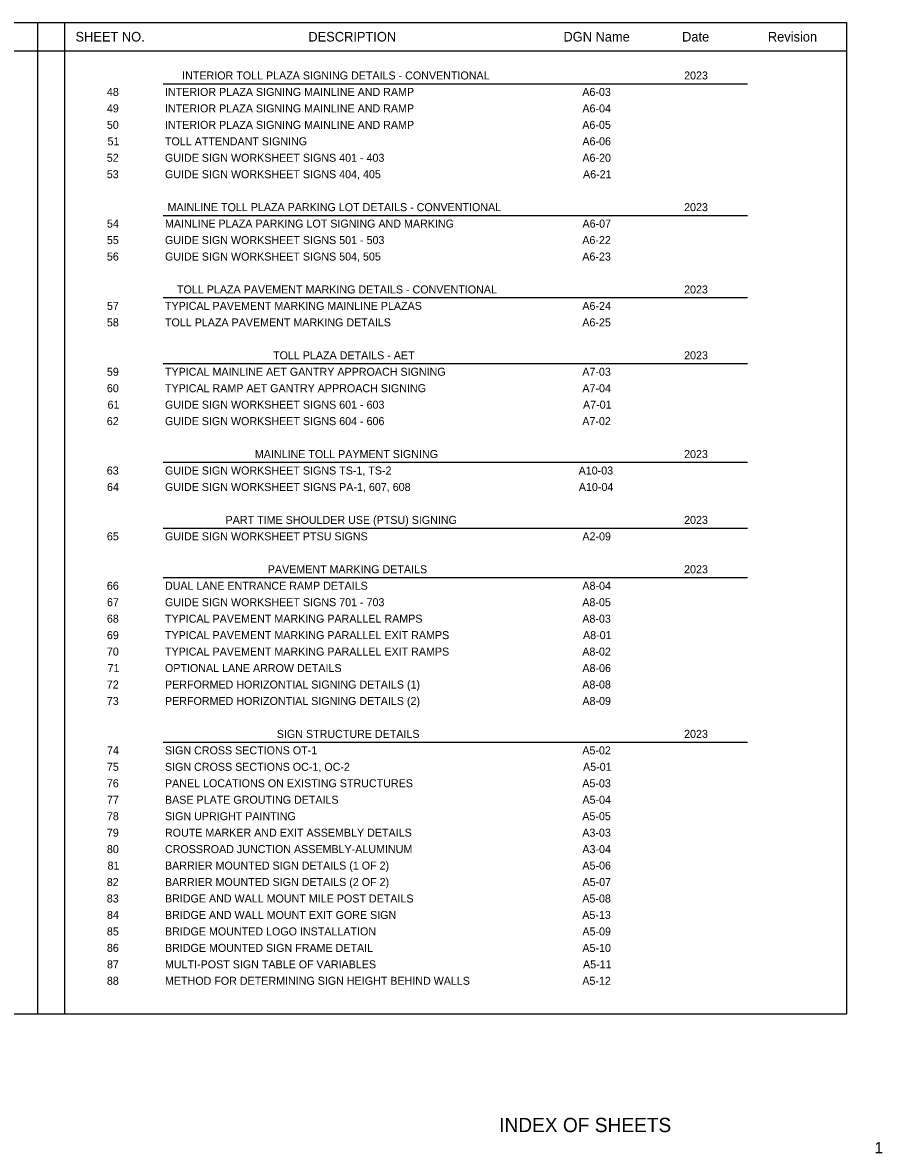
# Model space of a CAD drawing. Extents: x 2479979.8 to 2480018.9, y 3680687.9 to 3680700.6.
# Drawn here: x 2479989.84 to 2479999.24, y 3680688.19 to 3680700.55 of the extents above; entities that cross this region are included whole.
import ezdxf

# ---------------------------------------------------------------- set-up
doc = ezdxf.new("R2010")
doc.units = 0
for name, color, linetype in [('SumBoxLines_dp', 7, 'Continuous'), ('TextLabel', 7, 'Continuous'), ('TextMisc', 7, 'Continuous'), ('TextShtNo', 7, 'Continuous')]:
    doc.layers.add(name, color=color, linetype=linetype)

msp = doc.modelspace()

# ---------------------------------------------------------------- linework, layer by layer
at = {"layer": 'SumBoxLines_dp'}
for p, q in [((2479981.458, 3680700.555), (2479998.85, 3680700.555)), ((2479990.008, 3680700.555), (2479990.008, 3680689.717)), ((2479990.3, 3680700.555), (2479990.3, 3680690.167)), ((2479990.3, 3680700.555), (2479990.3, 3680689.717)), ((2479998.85, 3680700.555), (2479998.85, 3680689.717)), ((2479981.458, 3680700.247), (2479998.85, 3680700.247)), ((2479981.458, 3680700.247), (2479998.85, 3680700.247)), ((2479990.008, 3680700.247), (2479990.008, 3680691.427)), ((2479991.38, 3680699.887), (2479997.77, 3680699.887)), ((2479991.38, 3680699.887), (2479997.77, 3680699.887)), ((2479991.38, 3680698.447), (2479997.77, 3680698.447)), ((2479991.38, 3680698.447), (2479997.77, 3680698.447)), ((2479991.38, 3680697.547), (2479997.77, 3680697.547)), ((2479991.38, 3680697.547), (2479997.77, 3680697.547)), ((2479991.38, 3680696.827), (2479997.77, 3680696.827)), ((2479991.38, 3680696.827), (2479997.77, 3680696.827)), ((2479991.38, 3680695.747), (2479997.77, 3680695.747)), ((2479991.38, 3680695.747), (2479997.77, 3680695.747)), ((2479991.38, 3680695.027), (2479997.77, 3680695.027)), ((2479991.38, 3680695.027), (2479997.77, 3680695.027)), ((2479991.38, 3680694.487), (2479997.77, 3680694.487)), ((2479991.38, 3680694.487), (2479997.77, 3680694.487)), ((2479991.38, 3680692.687), (2479997.77, 3680692.687)), ((2479991.38, 3680692.687), (2479997.77, 3680692.687)), ((2479981.458, 3680689.717), (2479998.85, 3680689.717))]:
    msp.add_line(p, q, dxfattribs=at)

# ---------------------------------------------------------------- texts
at = {"layer": 'TextLabel'}
for s, height, p in [('SHEET NO.', 0.105, (2479990.422, 3680700.348)), ('DESCRIPTION', 0.105, (2479992.968, 3680700.348)), ('DGN Name', 0.105, (2479995.757, 3680700.348)), ('Date', 0.105, (2479997.054, 3680700.348)), ('Revision', 0.105, (2479997.992, 3680700.348)), ('INTERIOR TOLL PLAZA SIGNING DETAILS - CONVENTIONAL', 0.0875, (2479991.588, 3680699.933)), ('2023', 0.0875, (2479997.076, 3680699.933)), ('48', 0.0875, (2479990.765, 3680699.753)), ('INTERIOR PLAZA SIGNING MAINLINE AND RAMP', 0.0875, (2479991.4, 3680699.753)), ('A6-03', 0.0875, (2479995.963, 3680699.753)), ('49', 0.0875, (2479990.765, 3680699.573)), ('INTERIOR PLAZA SIGNING MAINLINE AND RAMP', 0.0875, (2479991.4, 3680699.573)), ('A6-04', 0.0875, (2479995.964, 3680699.573)), ('50', 0.0875, (2479990.765, 3680699.393)), ('INTERIOR PLAZA SIGNING MAINLINE AND RAMP', 0.0875, (2479991.4, 3680699.393)), ('A6-05', 0.0875, (2479995.963, 3680699.393)), ('51', 0.0875, (2479990.772, 3680699.213)), ('TOLL ATTENDANT SIGNING', 0.0875, (2479991.4, 3680699.213)), ('A6-06', 0.0875, (2479995.964, 3680699.213)), ('52', 0.0875, (2479990.764, 3680699.033)), ('GUIDE SIGN WORKSHEET SIGNS 401 - 403', 0.0875, (2479991.4, 3680699.033)), ('A6-20', 0.0875, (2479995.964, 3680699.033)), ('53', 0.0875, (2479990.764, 3680698.853)), ('GUIDE SIGN WORKSHEET SIGNS 404, 405', 0.0875, (2479991.4, 3680698.853)), ('A6-21', 0.0875, (2479995.971, 3680698.853)), ('MAINLINE TOLL PLAZA PARKING LOT DETAILS - CONVENTIONAL', 0.0875, (2479991.428, 3680698.493)), ('2023', 0.0875, (2479997.076, 3680698.493)), ('54', 0.0875, (2479990.766, 3680698.313)), ('MAINLINE PLAZA PARKING LOT SIGNING AND MARKING', 0.0875, (2479991.4, 3680698.313)), ('A6-07', 0.0875, (2479995.965, 3680698.313)), ('55', 0.0875, (2479990.765, 3680698.133)), ('GUIDE SIGN WORKSHEET SIGNS 501 - 503', 0.0875, (2479991.4, 3680698.133)), ('A6-22', 0.0875, (2479995.963, 3680698.133)), ('56', 0.0875, (2479990.765, 3680697.953)), ('GUIDE SIGN WORKSHEET SIGNS 504, 505', 0.0875, (2479991.4, 3680697.953)), ('A6-23', 0.0875, (2479995.963, 3680697.953)), ('TOLL PLAZA PAVEMENT MARKING DETAILS - CONVENTIONAL', 0.0875, (2479991.532, 3680697.593)), ('2023', 0.0875, (2479997.076, 3680697.593)), ('57', 0.0875, (2479990.766, 3680697.413)), ('TYPICAL PAVEMENT MARKING MAINLINE PLAZAS', 0.0875, (2479991.4, 3680697.413)), ('A6-24', 0.0875, (2479995.964, 3680697.413)), ('58', 0.0875, (2479990.765, 3680697.233)), ('TOLL PLAZA PAVEMENT MARKING DETAILS', 0.0875, (2479991.4, 3680697.233)), ('A6-25', 0.0875, (2479995.963, 3680697.233)), ('TOLL PLAZA DETAILS - AET', 0.0875, (2479992.582, 3680696.873)), ('2023', 0.0875, (2479997.076, 3680696.873)), ('59', 0.0875, (2479990.765, 3680696.693)), ('TYPICAL MAINLINE AET GANTRY APPROACH SIGNING', 0.0875, (2479991.4, 3680696.693)), ('A7-03', 0.0875, (2479995.963, 3680696.693)), ('60', 0.0875, (2479990.765, 3680696.513)), ('TYPICAL RAMP AET GANTRY APPROACH SIGNING', 0.0875, (2479991.4, 3680696.513)), ('A7-04', 0.0875, (2479995.964, 3680696.513)), ('61', 0.0875, (2479990.772, 3680696.333)), ('GUIDE SIGN WORKSHEET SIGNS 601 - 603', 0.0875, (2479991.4, 3680696.333)), ('A7-01', 0.0875, (2479995.971, 3680696.333)), ('62', 0.0875, (2479990.764, 3680696.153)), ('GUIDE SIGN WORKSHEET SIGNS 604 - 606', 0.0875, (2479991.4, 3680696.153)), ('A7-02', 0.0875, (2479995.963, 3680696.153)), ('MAINLINE TOLL PAYMENT SIGNING', 0.0875, (2479992.383, 3680695.793)), ('2023', 0.0875, (2479997.076, 3680695.793)), ('63', 0.0875, (2479990.764, 3680695.613)), ('GUIDE SIGN WORKSHEET SIGNS TS-1, TS-2', 0.0875, (2479991.4, 3680695.613)), ('A10-03', 0.0875, (2479995.923, 3680695.613)), ('64', 0.0875, (2479990.766, 3680695.433)), ('GUIDE SIGN WORKSHEET SIGNS PA-1, 607, 608', 0.0875, (2479991.4, 3680695.433)), ('A10-04', 0.0875, (2479995.925, 3680695.433)), ('PART TIME SHOULDER USE (PTSU) SIGNING', 0.0875, (2479992.063, 3680695.073)), ('2023', 0.0875, (2479997.076, 3680695.073)), ('65', 0.0875, (2479990.765, 3680694.893)), ('GUIDE SIGN WORKSHEET PTSU SIGNS', 0.0875, (2479991.4, 3680694.893)), ('A2-09', 0.0875, (2479995.964, 3680694.893)), ('PAVEMENT MARKING DETAILS', 0.0875, (2479992.524, 3680694.533)), ('2023', 0.0875, (2479997.076, 3680694.533)), ('66', 0.0875, (2479990.765, 3680694.353)), ('DUAL LANE ENTRANCE RAMP DETAILS', 0.0875, (2479991.4, 3680694.353)), ('A8-04', 0.0875, (2479995.964, 3680694.353)), ('67', 0.0875, (2479990.766, 3680694.173)), ('GUIDE SIGN WORKSHEET SIGNS 701 - 703', 0.0875, (2479991.4, 3680694.173)), ('A8-05', 0.0875, (2479995.963, 3680694.173)), ('68', 0.0875, (2479990.765, 3680693.993)), ('TYPICAL PAVEMENT MARKING PARALLEL RAMPS', 0.0875, (2479991.4, 3680693.993)), ('A8-03', 0.0875, (2479995.963, 3680693.993)), ('69', 0.0875, (2479990.765, 3680693.813)), ('TYPICAL PAVEMENT MARKING PARALLEL EXIT RAMPS', 0.0875, (2479991.4, 3680693.813)), ('A8-01', 0.0875, (2479995.971, 3680693.813)), ('70', 0.0875, (2479990.765, 3680693.633)), ('TYPICAL PAVEMENT MARKING PARALLEL EXIT RAMPS', 0.0875, (2479991.4, 3680693.633)), ('A8-02', 0.0875, (2479995.963, 3680693.633)), ('71', 0.0875, (2479990.772, 3680693.453)), ('OPTIONAL LANE ARROW DETAILS', 0.0875, (2479991.4, 3680693.453)), ('A8-06', 0.0875, (2479995.964, 3680693.453)), ('PERFORMED HORIZONTIAL SIGNING DETAILS (1)', 0.0875, (2479991.4, 3680693.273)), ('72', 0.0875, (2479990.764, 3680693.273)), ('A8-08', 0.0875, (2479995.963, 3680693.273)), ('73', 0.0875, (2479990.764, 3680693.093)), ('PERFORMED HORIZONTIAL SIGNING DETAILS (2)', 0.0875, (2479991.4, 3680693.093)), ('A8-09', 0.0875, (2479995.964, 3680693.093)), ('SIGN STRUCTURE DETAILS', 0.0875, (2479992.623, 3680692.733)), ('2023', 0.0875, (2479997.076, 3680692.733)), ('74', 0.0875, (2479990.766, 3680692.553)), ('SIGN CROSS SECTIONS OT-1', 0.0875, (2479991.4, 3680692.553)), ('A5-02', 0.0875, (2479995.963, 3680692.553)), ('75', 0.0875, (2479990.765, 3680692.373)), ('SIGN CROSS SECTIONS OC-1, OC-2', 0.0875, (2479991.4, 3680692.373)), ('A5-01', 0.0875, (2479995.971, 3680692.373)), ('76', 0.0875, (2479990.765, 3680692.193)), ('PANEL LOCATIONS ON EXISTING STRUCTURES', 0.0875, (2479991.4, 3680692.193)), ('A5-03', 0.0875, (2479995.963, 3680692.193)), ('77', 0.0875, (2479990.766, 3680692.013)), ('BASE PLATE GROUTING DETAILS', 0.0875, (2479991.4, 3680692.013)), ('A5-04', 0.0875, (2479995.964, 3680692.013)), ('78', 0.0875, (2479990.765, 3680691.833)), ('SIGN UPRIGHT PAINTING', 0.0875, (2479991.4, 3680691.833)), ('A5-05', 0.0875, (2479995.963, 3680691.833)), ('79', 0.0875, (2479990.765, 3680691.653)), ('ROUTE MARKER AND EXIT ASSEMBLY DETAILS', 0.0875, (2479991.4, 3680691.653)), ('A3-03', 0.0875, (2479995.963, 3680691.653)), ('80', 0.0875, (2479990.765, 3680691.473)), ('CROSSROAD JUNCTION ASSEMBLY-ALUMINUM', 0.0875, (2479991.4, 3680691.473)), ('A3-04', 0.0875, (2479995.964, 3680691.473)), ('BARRIER MOUNTED SIGN DETAILS (1 OF 2)', 0.0875, (2479991.4, 3680691.293)), ('81', 0.0875, (2479990.772, 3680691.293)), ('A5-06', 0.0875, (2479995.964, 3680691.293)), ('82', 0.0875, (2479990.764, 3680691.113)), ('BARRIER MOUNTED SIGN DETAILS (2 OF 2)', 0.0875, (2479991.4, 3680691.113)), ('A5-07', 0.0875, (2479995.965, 3680691.113)), ('83', 0.0875, (2479990.764, 3680690.933)), ('BRIDGE AND WALL MOUNT MILE POST DETAILS', 0.0875, (2479991.4, 3680690.933)), ('A5-08', 0.0875, (2479995.963, 3680690.933)), ('84', 0.0875, (2479990.766, 3680690.753)), ('BRIDGE AND WALL MOUNT EXIT GORE SIGN', 0.0875, (2479991.4, 3680690.753)), ('A5-13', 0.0875, (2479995.963, 3680690.753)), ('85', 0.0875, (2479990.765, 3680690.573)), ('BRIDGE MOUNTED LOGO INSTALLATION', 0.0875, (2479991.4, 3680690.573)), ('A5-09', 0.0875, (2479995.964, 3680690.573)), ('86', 0.0875, (2479990.765, 3680690.393)), ('BRIDGE MOUNTED SIGN FRAME DETAIL', 0.0875, (2479991.4, 3680690.393)), ('A5-10', 0.0875, (2479995.964, 3680690.393)), ('87', 0.0875, (2479990.766, 3680690.213)), ('MULTI-POST SIGN TABLE OF VARIABLES', 0.0875, (2479991.4, 3680690.213)), ('A5-11', 0.0875, (2479995.971, 3680690.213)), ('88', 0.0875, (2479990.765, 3680690.033)), ('METHOD FOR DETERMINING SIGN HEIGHT BEHIND WALLS', 0.0875, (2479991.4, 3680690.033)), ('A5-12', 0.0875, (2479995.963, 3680690.033))]:
    msp.add_text(s, height=height, dxfattribs=at).set_placement(p)
at = {"layer": 'TextMisc'}
msp.add_text('       INDEX OF SHEETS         ', height=0.15625, rotation=360, dxfattribs=at).set_placement((2479994.648, 3680688.422))
at = {"layer": 'TextShtNo'}
msp.add_text('  1   ', height=0.125, rotation=360, dxfattribs=at).set_placement((2479999.066, 3680688.19))

doc.saveas('drawing.dxf')
